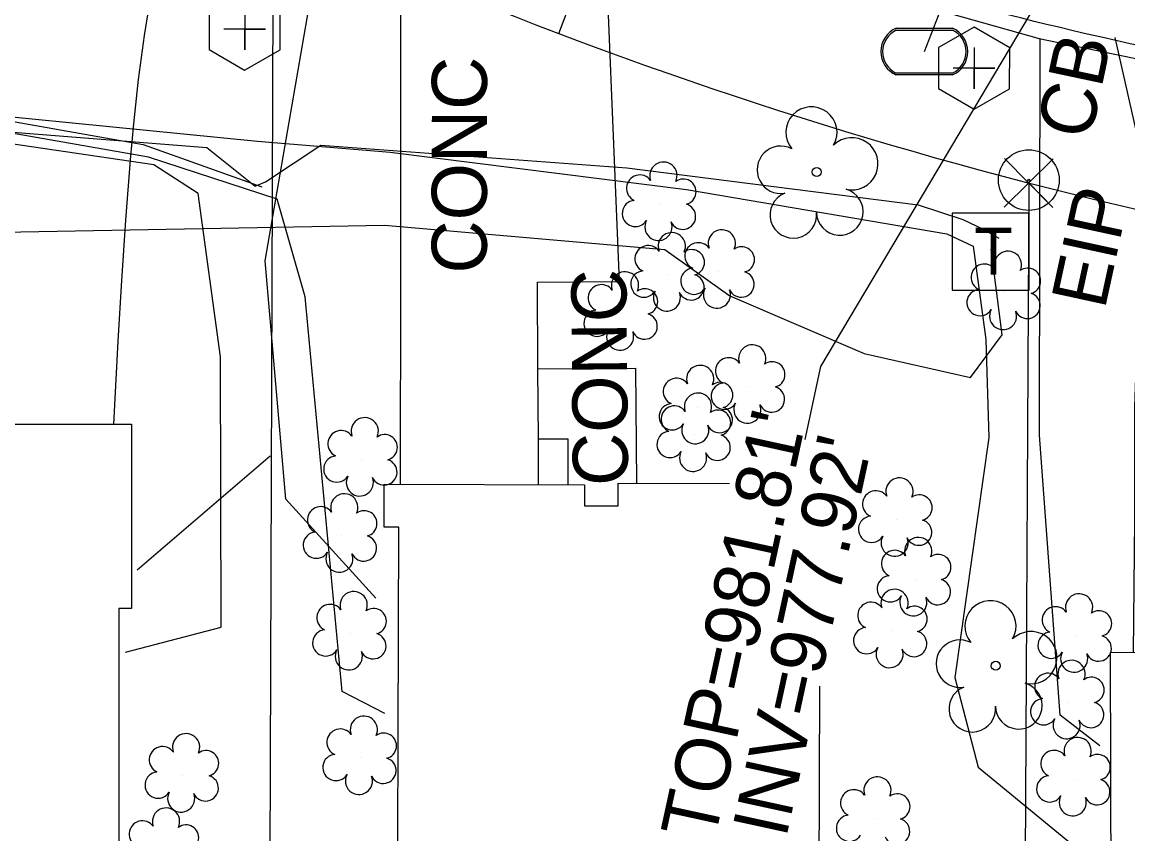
# Model space of a CAD drawing. Extents: x 1614611 to 1617571, y 898867 to 905462.
# Drawn here: x 1616405.6 to 1616485.9, y 901604.2 to 901663.2 of the extents above; entities that cross this region are included whole.
import ezdxf

# ---------------------------------------------------------------- set-up
doc = ezdxf.new("R2010")
doc.units = 0
for name, color, linetype in [('Exist Boundary Watershed Residential C 05', 7, 'Continuous'), ('Exist Building', 7, 'Continuous'), ('Exist Drainage Structure Drop Inlet CELL', 7, 'Continuous'), ('Exist Other Culture Area Outline', 7, 'Continuous'), ('Exist Other Culture Area Outline Text', 7, 'Continuous'), ('Exist Plan Preparation Watershed Yellow', 7, 'Continuous'), ('Exist Right of Way Width CELL', 7, 'Continuous'), ('Exist Roads EOP Other Text', 7, 'Continuous'), ('Exist Structure Minor Catch Basin Top Elevation', 7, 'Continuous'), ('Exist Structure Minor Pipes RCP 18 Inch Invert', 7, 'Continuous'), ('Exist Utilities Gas UG Line SUE LOS B', 7, 'Continuous'), ('Exist Utilities Telephone Pedestal CELL', 7, 'Continuous'), ('Exist Utilities Telephone UG FO SUE LOS B', 7, 'Continuous'), ('Exist Utilities TV UG Cable SUE LOS B', 7, 'Continuous'), ('Exist Utilities Water UG Line SUE LOS B', 7, 'Continuous'), ('Exist Vegetation Shrub CELL', 7, 'Continuous'), ('Exist Vegetation Tree CELL', 7, 'Continuous'), ('Prop Drainage Structure Catch Basin Grate 840 03E Label', 7, 'Continuous'), ('Prop Drainage Structure Pipe Alternate 30in Label', 7, 'Continuous'), ('Prop Drainage Structure Pipe Stub Out CELL', 7, 'Continuous'), ('Prop Drainage Structure Tops and Inverts LABEL', 7, 'Continuous'), ('Prop Earthen Structure Head Ditch Label', 7, 'Continuous'), ('Prop Easement Permanent Drainage', 7, 'Continuous'), ('Prop Plan Preparation Drainage Notes Label', 7, 'Continuous'), ('Prop SS Transition Line', 7, 'Continuous'), ('Scratch_Level_1', 7, 'Continuous'), ('Scratch_Level_9', 7, 'Continuous')]:
    doc.layers.add(name, color=color, linetype=linetype)

# ---------------------------------------------------------------- blocks, each defined once
blk = doc.blocks.new('EXIST PROPERTY IRON PIN')
at = {"layer": 'Exist Plan Preparation Watershed Yellow'}
for radius in [0.0441, 0.00141]:
    blk.add_circle((0, 0), radius, dxfattribs=at)
blk = doc.blocks.new('EXIST UTILITIES SANITARY SEWER CLEAN-OUT')
at = {"layer": 'Prop Drainage Structure Pipe Stub Out CELL'}
blk.add_line((0, 0), (0, 0), dxfattribs=at)
blk.add_lwpolyline([(-0.0516, 0.0299), (-0.0517, -0.0297), (-0.0001, -0.0596), (0.0516, -0.0299), (0.0517, 0.0297), (0.0001, 0.0596)], close=True, dxfattribs=at)
blk.add_lwpolyline([(0, 0.0302), (0, -0.0302), (0, 0), (0.0302, 0), (-0.0302, 0)], dxfattribs=at)
blk = doc.blocks.new('EXIST UTILITIES TELEPHONE PEDESTAL')
at = {"layer": 'Exist Utilities Telephone Pedestal CELL'}
blk.add_line((0, 0), (0, 0), dxfattribs=at)
blk.add_lwpolyline([(-0.0545, -0.0565), (0.0574, -0.0565), (0.0574, 0.0554), (-0.0545, 0.0554), (-0.0545, -0.0565)], dxfattribs=at)
blk.add_text('T', height=0.0684, dxfattribs=at).set_placement((-0.0226, -0.0343))
blk = doc.blocks.new('EXIST UTILITIES WATER METER')
at = {"layer": 'Prop SS Transition Line'}
blk.add_line((0, 0), (0, 0), dxfattribs=at)
for points in [[(-0.0408, 0.034), (0.0408, 0.034)], [(-0.0408, 0.0312), (0.0408, 0.0312)], [(0.0408, -0.0312), (-0.0413, -0.0312)], [(0.0408, -0.034), (-0.0413, -0.034)]]:
    blk.add_lwpolyline(points, dxfattribs=at)
for centre, radius, start, end in [((-0.0261, -0.0001), 0.0371, 113.178, 245.9794), ((0.0259, 0), 0.0371, 293.6483, 66.3084), ((-0.0259, -0.0001), 0.0347, 115.3009, 243.7824), ((0.0261, 0), 0.0345, 295.1272, 64.8728)]:
    blk.add_arc(centre, radius, start, end, dxfattribs=at)

msp = doc.modelspace()

# ---------------------------------------------------------------- linework, layer by layer
at = {"layer": 'Exist Boundary Watershed Residential C 05'}
msp.add_spline([(1616576.436, 901651.141), (1616560.362, 901651.873), (1616541.572, 901653.197), (1616514.262, 901656.474), (1616480.87, 901662.803), (1616452.549, 901670.884), (1616427.974, 901679.501)], degree=3, dxfattribs=at)
at = {"layer": 'Exist Building'}
for points in [[(1616394.898, 901627.651), (1616398.83, 901627.651), (1616398.829, 901633.968), (1616413.521, 901633.969), (1616413.522, 901620.575), (1616412.606, 901620.575), (1616412.608, 901591.698), (1616385.935, 901591.696), (1616385.933, 901610.332)], [(1616463.489, 901614.953), (1616463.395, 901587.068), (1616457.292, 901587.088), (1616457.264, 901578.691), (1616431.849, 901578.776), (1616431.883, 901588.687), (1616432.819, 901588.684), (1616432.946, 901626.485), (1616431.868, 901626.489), (1616431.878, 901629.618), (1616446.423, 901629.569), (1616446.418, 901628.051), (1616448.876, 901628.043), (1616448.881, 901629.683), (1616456.949, 901629.656)]]:
    msp.add_lwpolyline(points, dxfattribs=at)
msp.add_lwpolyline([(1616517.458, 901617.54), (1616517.599, 901573.704), (1616484.754, 901573.599), (1616484.614, 901617.397), (1616496.062, 901617.434), (1616496.048, 901621.76), (1616517.306, 901621.828), (1616517.32, 901617.539)], close=True, dxfattribs=at)
at = {"layer": 'Exist Other Culture Area Outline'}
for points in [[(1616443.048, 901637.997), (1616450.123, 901638.046), (1616450.194, 901629.679)], [(1616443.075, 901632.906), (1616445.208, 901632.905), (1616445.224, 901629.573)]]:
    msp.add_lwpolyline(points, dxfattribs=at)
at = {"layer": 'Exist Right of Way Width CELL'}
msp.add_line((1616444.555, 901662.356), (1616453.449, 901685.778), dxfattribs=at)
at = {"layer": 'Exist Utilities Gas UG Line SUE LOS B'}
msp.add_line((1616413.941, 901623.385), (1616423.596, 901631.665), dxfattribs=at)
for points in [[(1616326.476, 901676.736), (1616348.676, 901680.409), (1616373.137, 901686.793), (1616383.025, 901688.182), (1616402.076, 901686.65), (1616424.003, 901679.778), (1616450.549, 901670.159), (1616479.448, 901661.996), (1616512.172, 901655.218), (1616540.791, 901649.287), (1616561.301, 901640.128), (1616569.634, 901633.987), (1616582.757, 901628.459), (1616598.916, 901622.957)], [(1616431.279, 901621.331), (1616424.74, 901628.52), (1616423.23, 901645.841), (1616426.723, 901666.015), (1616429.548, 901678.085)], [(1616483.844, 901610.622), (1616480.965, 901612.831), (1616479.461, 901633.18), (1616479.526, 901661.974)]]:
    msp.add_lwpolyline(points, dxfattribs=at)
at = {"layer": 'Exist Utilities Telephone UG FO SUE LOS B'}
msp.add_lwpolyline([(1616320.939, 901651.383), (1616362.887, 901649.358), (1616380.365, 901647.483), (1616431.909, 901648.438), (1616452.27, 901646.672), (1616456.985, 901643.309), (1616466.723, 901639.114), (1616474.447, 901637.354), (1616476.764, 901640.469), (1616475.96, 901646.691)], dxfattribs=at)
at = {"layer": 'Exist Utilities TV UG Cable SUE LOS B'}
for points in [[(1616322.594, 901658.961), (1616339.795, 901659.859), (1616360.734, 901661.282), (1616382.487, 901659.929), (1616414.384, 901654.293), (1616422.982, 901651.209)], [(1616322.652, 901659.227), (1616355.195, 901661.085), (1616371.732, 901661.161), (1616395.914, 901657.717), (1616402.743, 901655.366), (1616419.005, 901654.07), (1616422.504, 901651.267), (1616423.268, 901651.588), (1616427.27, 901654.253), (1616449.491, 901652.608), (1616470.665, 901649.916), (1616473.894, 901648.847), (1616475.375, 901648.133), (1616476.522, 901647.481)]]:
    msp.add_lwpolyline(points, dxfattribs=at)
at = {"layer": 'Exist Utilities Water UG Line SUE LOS B'}
msp.add_line((1616471.106, 901661.04), (1616476.068, 901673.701), dxfattribs=at)
at = {"layer": 'Exist Vegetation Shrub CELL'}
for p, q in [((1616451.925, 901649.987), (1616451.925, 901649.987)), ((1616452.538, 901644.858), (1616452.538, 901644.858)), ((1616456.17, 901645.065), (1616456.17, 901645.065)), ((1616476.949, 901643.511), (1616476.949, 901643.511)), ((1616449.139, 901642.015), (1616449.139, 901642.015)), ((1616458.382, 901636.712), (1616458.382, 901636.712)), ((1616454.597, 901635.219), (1616454.597, 901635.219)), ((1616454.44, 901633.208), (1616454.44, 901633.208)), ((1616430.237, 901631.422), (1616430.237, 901631.422)), ((1616469.071, 901627.042), (1616469.071, 901627.042)), ((1616428.752, 901625.891), (1616428.752, 901625.891)), ((1616470.436, 901622.719), (1616470.436, 901622.719)), ((1616468.712, 901618.953), (1616468.712, 901618.953)), ((1616429.436, 901618.791), (1616429.436, 901618.791)), ((1616482.113, 901618.625), (1616482.113, 901618.625)), ((1616481.566, 901613.794), (1616481.566, 901613.794)), ((1616430.171, 901609.741), (1616430.171, 901609.741)), ((1616417.264, 901608.467), (1616417.264, 901608.467)), ((1616482.01, 901608.189), (1616482.01, 901608.189)), ((1616467.47, 901605.329), (1616467.47, 901605.329))]:
    msp.add_line(p, q, dxfattribs=at)
for centre, radius, start, end in [((1616452.154, 901652.027), 0.99, 334.83907, 200.47174), ((1616450.442, 901651.114), 0.968, 35.89076, 245.42165), ((1616453.597, 901650.856), 0.929, 284.45672, 126.08612), ((1616450.124, 901649.282), 0.955, 95.10992, 327.95341), ((1616453.562, 901649.058), 0.937, 204.99133, 73.46012), ((1616451.796, 901648.303), 0.984, 151.27966, 21.38702), ((1616452.766, 901646.899), 0.99, 334.83907, 200.47174), ((1616456.398, 901647.106), 0.99, 334.83907, 200.47174), ((1616454.687, 901646.192), 0.968, 35.89076, 245.42165), ((1616451.055, 901645.985), 0.968, 35.89076, 245.42165), ((1616454.21, 901645.727), 0.929, 284.45672, 126.08612), ((1616457.842, 901645.934), 0.929, 284.45672, 126.08612), ((1616477.178, 901645.551), 0.99, 334.83907, 200.47174), ((1616475.467, 901644.637), 0.968, 35.89076, 245.42165), ((1616449.368, 901644.056), 0.99, 334.83907, 200.47174), ((1616450.737, 901644.154), 0.955, 95.10992, 327.95341), ((1616454.175, 901643.929), 0.937, 204.99133, 73.46012), ((1616454.369, 901644.361), 0.955, 95.10992, 327.95341), ((1616457.807, 901644.136), 0.937, 204.99133, 73.46012), ((1616478.621, 901644.379), 0.929, 284.45672, 126.08612), ((1616447.656, 901643.142), 0.968, 35.89076, 245.42165), ((1616450.811, 901642.884), 0.929, 284.45672, 126.08612), ((1616456.041, 901643.382), 0.984, 151.27966, 21.38702), ((1616452.409, 901643.175), 0.984, 151.27966, 21.38702), ((1616475.149, 901642.806), 0.955, 95.10992, 327.95341), ((1616478.586, 901642.582), 0.937, 204.99133, 73.46012), ((1616447.339, 901641.311), 0.955, 95.10992, 327.95341), ((1616476.821, 901641.827), 0.984, 151.27966, 21.38702), ((1616450.776, 901641.086), 0.937, 204.99133, 73.46012), ((1616449.01, 901640.332), 0.984, 151.27966, 21.38702), ((1616458.61, 901638.752), 0.99, 334.83907, 200.47174), ((1616454.826, 901637.26), 0.99, 334.83907, 200.47174), ((1616456.899, 901637.838), 0.968, 35.89076, 245.42165), ((1616460.054, 901637.581), 0.929, 284.45672, 126.08612), ((1616453.114, 901636.346), 0.968, 35.89076, 245.42165), ((1616456.581, 901636.007), 0.955, 95.10992, 327.95341), ((1616456.269, 901636.088), 0.929, 284.45672, 126.08612), ((1616460.019, 901635.783), 0.937, 204.99133, 73.46012), ((1616454.668, 901635.248), 0.99, 334.83907, 200.47174), ((1616452.796, 901634.515), 0.955, 95.10992, 327.95341), ((1616452.957, 901634.335), 0.968, 35.89076, 245.42165), ((1616456.234, 901634.29), 0.937, 204.99133, 73.46012), ((1616456.112, 901634.077), 0.929, 284.45672, 126.08612), ((1616458.253, 901635.028), 0.984, 151.27966, 21.38702), ((1616430.466, 901633.462), 0.99, 334.83907, 200.47174), ((1616428.755, 901632.548), 0.968, 35.89076, 245.42165), ((1616452.639, 901632.503), 0.955, 95.10992, 327.95341), ((1616454.468, 901633.536), 0.984, 151.27966, 21.38702), ((1616431.909, 901632.291), 0.929, 284.45672, 126.08612), ((1616456.077, 901632.279), 0.937, 204.99133, 73.46012), ((1616454.311, 901631.524), 0.984, 151.27966, 21.38702), ((1616428.437, 901630.717), 0.955, 95.10992, 327.95341), ((1616431.874, 901630.493), 0.937, 204.99133, 73.46012), ((1616430.109, 901629.738), 0.984, 151.27966, 21.38702), ((1616469.3, 901629.083), 0.99, 334.83907, 200.47174), ((1616428.981, 901627.931), 0.99, 334.83907, 200.47174), ((1616467.589, 901628.169), 0.968, 35.89076, 245.42165), ((1616470.743, 901627.911), 0.929, 284.45672, 126.08612), ((1616427.27, 901627.018), 0.968, 35.89076, 245.42165), ((1616430.424, 901626.76), 0.929, 284.45672, 126.08612), ((1616467.271, 901626.338), 0.955, 95.10992, 327.95341), ((1616470.709, 901626.113), 0.937, 204.99133, 73.46012), ((1616426.952, 901625.187), 0.955, 95.10992, 327.95341), ((1616430.389, 901624.962), 0.937, 204.99133, 73.46012), ((1616468.943, 901625.359), 0.984, 151.27966, 21.38702), ((1616470.665, 901624.759), 0.99, 334.83907, 200.47174), ((1616428.624, 901624.207), 0.984, 151.27966, 21.38702), ((1616468.953, 901623.845), 0.968, 35.89076, 245.42165), ((1616472.108, 901623.588), 0.929, 284.45672, 126.08612), ((1616468.636, 901622.014), 0.955, 95.10992, 327.95341), ((1616472.073, 901621.79), 0.937, 204.99133, 73.46012), ((1616429.665, 901620.832), 0.99, 334.83907, 200.47174), ((1616468.941, 901620.993), 0.99, 334.83907, 200.47174), ((1616470.308, 901621.035), 0.984, 151.27966, 21.38702), ((1616482.342, 901620.665), 0.99, 334.83907, 200.47174), ((1616427.954, 901619.918), 0.968, 35.89076, 245.42165), ((1616431.108, 901619.66), 0.929, 284.45672, 126.08612), ((1616467.23, 901620.08), 0.968, 35.89076, 245.42165), ((1616470.384, 901619.822), 0.929, 284.45672, 126.08612), ((1616480.631, 901619.751), 0.968, 35.89076, 245.42165), ((1616483.785, 901619.493), 0.929, 284.45672, 126.08612), ((1616427.636, 901618.087), 0.955, 95.10992, 327.95341), ((1616466.912, 901618.248), 0.955, 95.10992, 327.95341), ((1616470.349, 901618.024), 0.937, 204.99133, 73.46012), ((1616431.074, 901617.862), 0.937, 204.99133, 73.46012), ((1616480.313, 901617.92), 0.955, 95.10992, 327.95341), ((1616483.75, 901617.696), 0.937, 204.99133, 73.46012), ((1616429.308, 901617.108), 0.984, 151.27966, 21.38702), ((1616468.584, 901617.269), 0.984, 151.27966, 21.38702), ((1616481.985, 901616.941), 0.984, 151.27966, 21.38702), ((1616481.795, 901615.834), 0.99, 334.83907, 200.47174), ((1616480.083, 901614.92), 0.968, 35.89076, 245.42165), ((1616483.238, 901614.663), 0.929, 284.45672, 126.08612), ((1616479.766, 901613.089), 0.955, 95.10992, 327.95341), ((1616483.203, 901612.865), 0.937, 204.99133, 73.46012), ((1616430.4, 901611.781), 0.99, 334.83907, 200.47174), ((1616481.438, 901612.11), 0.984, 151.27966, 21.38702), ((1616428.689, 901610.868), 0.968, 35.89076, 245.42165), ((1616417.492, 901610.507), 0.99, 334.83907, 200.47174), ((1616431.843, 901610.61), 0.929, 284.45672, 126.08612), ((1616482.239, 901610.23), 0.99, 334.83907, 200.47174), ((1616415.781, 901609.593), 0.968, 35.89076, 245.42165), ((1616418.936, 901609.336), 0.929, 284.45672, 126.08612), ((1616480.527, 901609.316), 0.968, 35.89076, 245.42165), ((1616428.371, 901609.037), 0.955, 95.10992, 327.95341), ((1616431.808, 901608.812), 0.937, 204.99133, 73.46012), ((1616483.682, 901609.058), 0.929, 284.45672, 126.08612), ((1616415.463, 901607.762), 0.955, 95.10992, 327.95341), ((1616430.043, 901608.057), 0.984, 151.27966, 21.38702), ((1616418.901, 901607.538), 0.937, 204.99133, 73.46012), ((1616467.699, 901607.37), 0.99, 334.83907, 200.47174), ((1616480.21, 901607.485), 0.955, 95.10992, 327.95341), ((1616483.647, 901607.26), 0.937, 204.99133, 73.46012), ((1616417.135, 901606.783), 0.984, 151.27966, 21.38702), ((1616465.987, 901606.456), 0.968, 35.89076, 245.42165), ((1616469.142, 901606.198), 0.929, 284.45672, 126.08612), ((1616481.882, 901606.505), 0.984, 151.27966, 21.38702), ((1616416.035, 901605.11), 0.99, 334.83907, 200.47174), ((1616465.67, 901604.625), 0.955, 95.10992, 327.95341), ((1616469.107, 901604.4), 0.937, 204.99133, 73.46012), ((1616414.324, 901604.197), 0.968, 35.89076, 245.42165), ((1616417.479, 901603.939), 0.929, 284.45672, 126.08612)]:
    msp.add_arc(centre, radius, start, end, dxfattribs=at)
at = {"layer": 'Exist Vegetation Tree CELL'}
for p, q in [((1616463.292, 901652.298), (1616463.292, 901652.298)), ((1616476.291, 901616.425), (1616476.291, 901616.425))]:
    msp.add_line(p, q, dxfattribs=at)
for centre in [(1616463.292, 901652.298), (1616476.291, 901616.425)]:
    msp.add_circle(centre, 0.326, dxfattribs=at)
for centre, radius, start, end in [((1616462.907, 901655.172), 1.856, 330.16508, 219.71335), ((1616465.841, 901652.887), 1.899, 257.1011, 134.19993), ((1616460.687, 901652.452), 1.727, 62.66361, 279.3457), ((1616464.965, 901649.399), 1.698, 181.28216, 74.55999), ((1616461.588, 901649.178), 1.689, 111.56708, 6.23104), ((1616475.906, 901619.298), 1.856, 330.16508, 219.71335), ((1616478.84, 901617.013), 1.899, 257.1011, 134.19993), ((1616473.686, 901616.579), 1.727, 62.66361, 279.3457), ((1616477.964, 901613.525), 1.698, 181.28216, 74.55999), ((1616474.587, 901613.304), 1.689, 111.56708, 6.23104)]:
    msp.add_arc(centre, radius, start, end, dxfattribs=at)
at = {"layer": 'Prop Drainage Structure Catch Basin Grate 840 03E Label'}
for points in [[(1616322.129, 901656.828), (1616339.438, 901657.54), (1616355.254, 901660.311), (1616371.586, 901660.692), (1616392.859, 901657.485), (1616422.684, 901654.528), (1616432.316, 901653.731), (1616453.833, 901651.02), (1616472.739, 901647.791), (1616474.659, 901646.901), (1616475.563, 901640.136), (1616475.797, 901633.012), (1616473.32, 901615.576), (1616475.015, 901609.049), (1616484.66, 901601.148)], [(1616431.929, 901612.971), (1616428.819, 901614.563), (1616426.151, 901643.219), (1616424.095, 901650.319), (1616414.764, 901653.361), (1616392.769, 901657.217), (1616371.385, 901660.505), (1616355.218, 901660.133), (1616340.06, 901657.556), (1616322.037, 901656.408)], [(1616413.087, 901617.407), (1616420.044, 901619.219), (1616419.981, 901638.866), (1616418.361, 901650.741), (1616415.145, 901652.817), (1616393.412, 901656.01), (1616371.662, 901659.29), (1616355.743, 901659.03), (1616340.12, 901656.384), (1616321.804, 901655.34)]]:
    msp.add_lwpolyline(points, dxfattribs=at)
at = {"layer": 'Prop Drainage Structure Pipe Alternate 30in Label'}
for p, q in [((1616423.205, 901496.843), (1616423.837, 901670.831)), ((1616478.69, 901651.495), (1616477.825, 901496.627))]:
    msp.add_line(p, q, dxfattribs=at)
at = {"layer": 'Prop Drainage Structure Tops and Inverts LABEL'}
msp.add_line((1616478.69, 901651.495), (1616478.69, 901651.495), dxfattribs=at)
msp.add_lwpolyline([(1616476.932, 901653.273), (1616480.448, 901649.717), (1616478.69, 901651.495), (1616480.467, 901653.253), (1616476.912, 901649.737)], dxfattribs=at)
at = {"layer": 'Prop Earthen Structure Head Ditch Label'}
msp.add_arc((1616560.484, 901967.642), 326.557, 246.2087, 265.2858, dxfattribs=at)
at = {"layer": 'Prop Plan Preparation Drainage Notes Label'}
msp.add_lwpolyline([(1616479.393, 901664.827), (1616463.567, 901638.167), (1616462.425, 901632.862)], dxfattribs=at)
at = {"layer": 'Scratch_Level_1'}
for points in [[(1616412.253, 901633.969), (1616412.563, 901640.017), (1616412.82, 901644.408), (1616413.119, 901648.794), (1616413.462, 901653.175), (1616413.689, 901655.803), (1616414.047, 901659.005), (1616414.479, 901662.199), (1616414.984, 901665.385), (1616415.561, 901668.56), (1616416.086, 901671.026)], [(1616433.067, 901629.614), (1616433.076, 901644.726), (1616433.098, 901669.403)], [(1616443.093, 901629.58), (1616443.075, 901632.906), (1616443.048, 901637.997), (1616443.015, 901644.283), (1616448.973, 901644.349), (1616448.154, 901664.293)], [(1616486.283, 901617.402), (1616486.381, 901626.996), (1616486.398, 901635.24), (1616486.564, 901640.136), (1616486.917, 901653.403), (1616484.967, 901662.054)]]:
    msp.add_lwpolyline(points, dxfattribs=at)
at = {"layer": 'Scratch_Level_9'}
msp.add_spline([(1616600.703, 901615.071), (1616596.491, 901640.707), (1616577.816, 901651.88), (1616577.758, 901653.582), (1616560.382, 901654.399), (1616541.66, 901655.742), (1616514.624, 901658.966), (1616481.568, 901665.456), (1616453.293, 901673.284), (1616429.007, 901681.848), (1616427.559, 901682.356), (1616413.543, 901687.442), (1616400.429, 901690.536), (1616382.846, 901691.642), (1616359.811, 901688.156), (1616349.758, 901685.257), (1616334.537, 901681.299), (1616320.225, 901678.765)], degree=3, dxfattribs=at)

# ---------------------------------------------------------------- block references
at = {"layer": 'Exist Plan Preparation Watershed Yellow', "xscale": 50, "yscale": 50}
msp.add_blockref('EXIST PROPERTY IRON PIN', (1616478.691, 901651.705), dxfattribs=at)
at = {"layer": 'Exist Utilities Telephone Pedestal CELL', "xscale": 50, "yscale": 50}
msp.add_blockref('EXIST UTILITIES TELEPHONE PEDESTAL', (1616475.856, 901646.545), dxfattribs=at)
at = {"layer": 'Prop Drainage Structure Pipe Stub Out CELL', "xscale": 50, "yscale": 50}
for p in [(1616421.75, 901662.667), (1616474.72, 901659.836)]:
    msp.add_blockref('EXIST UTILITIES SANITARY SEWER CLEAN-OUT', p, dxfattribs=at)
at = {"layer": 'Prop SS Transition Line', "xscale": 50, "yscale": 50}
msp.add_blockref('EXIST UTILITIES WATER METER', (1616471.106, 901661.04), dxfattribs=at)

# ---------------------------------------------------------------- texts
at = {"layer": 'Exist Drainage Structure Drop Inlet CELL'}
msp.add_text('EIP', height=4, rotation=77.71667, dxfattribs=at).set_placement((1616484.201, 901642.226))
at = {"layer": 'Exist Other Culture Area Outline Text'}
msp.add_text('CONC', height=4, rotation=90.48265, dxfattribs=at).set_placement((1616449.59, 901629.506))
at = {"layer": 'Exist Roads EOP Other Text'}
msp.add_text('CONC', height=4, rotation=89.94892, dxfattribs=at).set_placement((1616439.328, 901644.916))
at = {"layer": 'Exist Structure Minor Catch Basin Top Elevation'}
msp.add_text("TOP=981.81'", height=4, rotation=77.71667, dxfattribs=at).set_placement((1616455.852, 901603.6))
at = {"layer": 'Exist Structure Minor Pipes RCP 18 Inch Invert'}
msp.add_text("INV=977.92'", height=4, rotation=77.71667, dxfattribs=at).set_placement((1616461.063, 901603.828))
at = {"layer": 'Prop Easement Permanent Drainage'}
msp.add_text('CB', height=4, rotation=78.01667, dxfattribs=at).set_placement((1616483.159, 901654.522))

doc.saveas('drawing.dxf')
